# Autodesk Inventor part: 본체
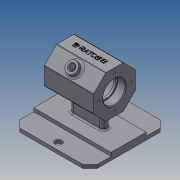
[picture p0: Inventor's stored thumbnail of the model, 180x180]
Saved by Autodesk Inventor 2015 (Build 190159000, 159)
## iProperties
Created: 2018-06
Part Number: 본체
Material: 일반
Document SubType Name: Modeling
Designer: 임동건
Density: 1 g/cm^3
Appearance: 기본값
Mass: 204.445 g
Surface Area: 601.877 cm^2
Volume: 204.445 cm^3
Author: 임동건
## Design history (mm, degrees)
sketch "스케치1"
  geometry: L1 (-55, 55)-(55, 55); L2 (55, 55)-(55, -55); L3 (55, -55)-(-55, -55); L4 (-55, -55)-(-55, 55); L5 (-55, 25)-(55, 25); L6 (55, 25)-(55, -25); L7 (55, -25)-(-55, -25); L8 (-55, -25)-(-55, 25); L9 (-19, 0)-(19, 0); L10 (-19, -5)-(19, -5); L11 (19, 5)-(-19, 5); C1 r 5 at (0, 45); C2 r 5 at (0, -45); A1 r 5 centre (-19, 0) between (-19, 5) and (-19, -5); A2 r 5 centre (19, 0) between (19, -5) and (19, 5); 5 further points
  constraints: 24 end point, 5 parallel, 4 centre point, 4 midpoint, 4 point on circle, 4 tangent, 3 horizontal, 3 vertical alignment, 2 horizontal alignment, 2 perpendicular, 2 point on line, 1 coincident
  dimensions: "d0" = 110 distance between parallel lines of L3 L1; "d1" = 110 distance between parallel lines of L2 L4; "d3" = 30 distance between parallel lines of L5 L1; "d4" = 10 diameter of C1; "d5" = 10 diameter of C2; "d6" = 10 distance from line of L1 C1.centre; "d7" = 10 distance from line of L3 C2.centre; "d8" = 5 radius of A2; "d9" = 38 distance of L9.end L9.start
extrude "돌출1" new body sketch "스케치1" distance "d10" = 5; taper "d11" = 0 deg
extrude "돌출2" join sketch "스케치1" distance "d12" = 10; taper "d13" = 0 deg
chamfer "모따기1" distance "d14" = 10; stored, may be unused: second distance "d15" = 2, angle "d16" = 45 deg
extrude "돌출3" join sketch "스케치1" distance "d17" = 32; taper "d18" = 0 deg
sketch "스케치2"
  geometry: L1 (-30, 49.574)-(-30, 74.426); L2 (-30, 74.426)-(-12.426, 92); L3 (-12.426, 92)-(12.426, 92); L4 (12.426, 92)-(30, 74.426); L5 (30, 74.426)-(30, 49.574); L6 (30, 49.574)-(12.426, 32); L7 (12.426, 32)-(-12.426, 32); L8 (-12.426, 32)-(-30, 49.574); L9 (-45, 0)-(45, 0) reference; C1 r 25 at (0, 62); 4 further points
  constraints: 16 end point, 3 vertical alignment, 2 midpoint, 1 centre point, 1 coincident, 17 other
  dimensions: "d19" = 62 distance of point (0, 0) point (0, 62); "d20" = 92 distance between parallel lines of L9 L3; "d22" = 50 diameter of C1
extrude "돌출4" join sketch "스케치2" stored distance "d23" = 70; taper "d24" = 0 deg
extrude "돌출5" cut sketch "스케치2" stored distance "d25" = 40; taper "d26" = 0 deg
sketch "스케치3"
  geometry: L1 (49.574, -30)-(74.426, -30) reference; L2 (74.426, -30)-(92, -12.426) reference; L3 (92, -12.426)-(92, 12.426) reference; L4 (92, 12.426)-(74.426, 30) reference; L5 (74.426, 30)-(49.574, 30) reference; L6 (49.574, 30)-(32, 12.426) reference; L7 (32, 12.426)-(32, -12.426) reference; L8 (32, -12.426)-(49.574, -30) reference; L9 (0, 45)-(0, -45) reference; C1 r 16 at (62, 0); C2 r 14 at (62, 0); 2 further points
  constraints: 2 centre point, 1 horizontal alignment, 1 midpoint
  dimensions: "d27" = 32 diameter of C1; "d28" = 62 distance from line of L9 C1.centre; "d29" = 28 diameter of C2
  node "투영된 루프1"
extrude "돌출6" cut sketch "스케치3" distance "d30" = 12; taper "d31" = 0 deg
extrude "돌출7" cut sketch "스케치3" stored distance "d32" = 12; taper "d33" = 0 deg
sketch "스케치4"
  geometry: L1 (0, 0)-(0, 24.853) reference; C1 r 8 at (35, 12.426); 2 further points
  constraints: 1 centre point, 1 horizontal alignment, 1 midpoint, 1 vertical alignment
  dimensions: "d34" = 16 diameter of C1
extrude "돌출8" join sketch "스케치4" distance "d35" = 7; taper "d36" = 0 deg
hole "구멍1" diameter "d39" = 8; stored, may be unused: countersink angle "d43" = 90 deg, drill point angle "d45" = 0 deg; dims "d37" = 10, "d38" = 10, "d40" = 6, "d41" = 8, "d42" = 2, "d44" = 15
fillet "모깎기1" dims "d46" = 1
fillet "모깎기2" dims "d47" = 3
fillet "모깎기5" dims "d50" = 2
fillet "모깎기6" dims "d51" = 0.3
sketch "스케치5"
  geometry: L1 (0, 45)-(0, -45) reference; L2 (32, 12.012)-(32, -12.012) reference; L3 (32.293, -12.719)-(49.281, -29.707) reference; L4 (49.988, -30)-(74.012, -30) reference; L5 (74.719, -29.707)-(91.707, -12.719) reference; L6 (92, -12.012)-(92, 12.012) reference; L7 (91.707, 12.719)-(74.719, 29.707) reference; L8 (74.012, 30)-(49.988, 30) reference; L9 (49.281, 29.707)-(32.293, 12.719) reference; C1 r 16 at (62, 0) reference; A1 r 1 centre (33, 12.012) between (32.293, 12.719) and (32, 12.012) reference; A2 r 1 centre (33, -12.012) between (32, -12.012) and (32.293, -12.719) reference; A3 r 1 centre (49.988, -29) between (49.281, -29.707) and (49.988, -30) reference; A4 r 1 centre (74.012, -29) between (74.012, -30) and (74.719, -29.707) reference; A5 r 1 centre (91, -12.012) between (91.707, -12.719) and (92, -12.012) reference; A6 r 1 centre (91, 12.012) between (92, 12.012) and (91.707, 12.719) reference; A7 r 1 centre (74.012, 29) between (74.719, 29.707) and (74.012, 30) reference; A8 r 1 centre (49.988, 29) between (49.988, 30) and (49.281, 29.707) reference; 3 further points
  constraints: 1 horizontal alignment, 1 midpoint
  dimensions: "d52" = 23 distance of C1.centre point (85, 0)
hole "구멍2" sketch "스케치5" at (85, 0) diameter "d53" = 3.242; stored, may be unused: countersink angle "d57" = 90 deg, drill point angle "d59" = 120 deg; dims "d54" = 8, "d55" = 8, "d56" = 2, "d58" = 10
sketch "스케치6"
  geometry: L1 (10.908, -8.635)-(59.092, -8.635); L2 (59.092, -8.635)-(59.092, -15.389); L3 (59.092, -15.389)-(10.908, -15.389); L4 (10.908, -15.389)-(10.908, -8.635); L5 (70, 0)-(70, -24.024) reference; 5 further points
  constraints: 3 midpoint, 1 coincident, 1 horizontal alignment, 1 vertical alignment, 2 other
feature "엠보싱1" sketch "스케치6" dims "d0" = 110, "d1" = 110, "d3" = 30, "d4" = 10, "d5" = 10, "d6" = 10, "d7" = 10, "d63" = 0.5, "d64" = 0
chamfer "모따기2" distance "d65" = 1; stored, may be unused: second distance "d66" = 2, angle "d67" = 45 deg
chamfer "모따기3" distance "d68" = 1; stored, may be unused: second distance "d69" = 2, angle "d70" = 45 deg
fillet "모깎기7" dims "d71" = 3
node "솔리드1"
mirror "대칭1"
pattern_circular "원형 패턴1" dims angle "d61" = 360 deg
mirror "대칭2"
node "투영된 루프2"
